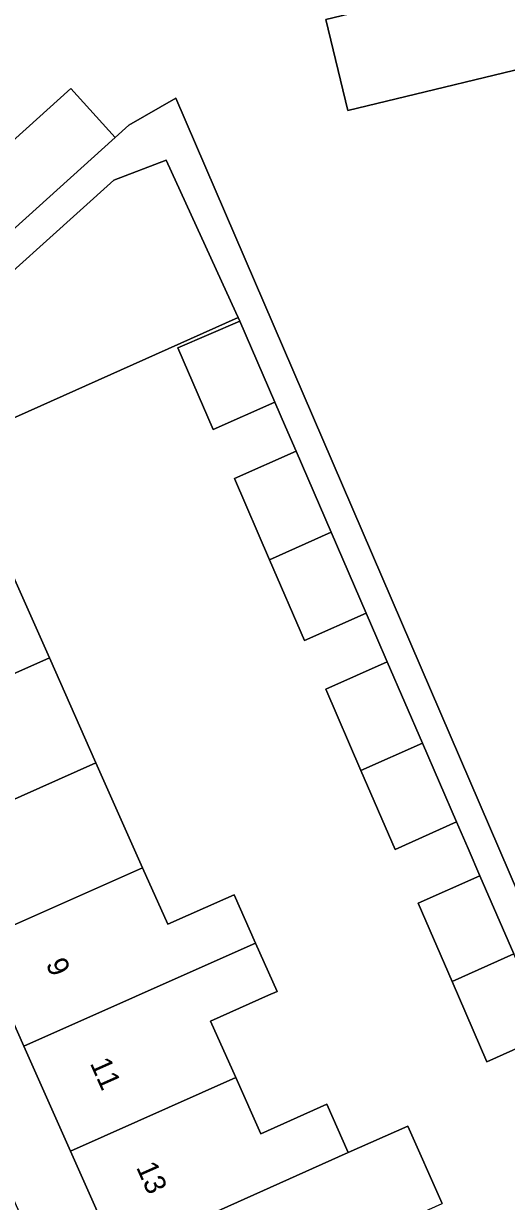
# Model space of a CAD drawing. Extents: x 163147 to 163550, y 380933 to 381639.
# Drawn here: x 163282.6 to 163305.4, y 381197.5 to 381253.2 of the extents above; entities that cross this region are included whole.
import ezdxf

# ---------------------------------------------------------------- set-up
doc = ezdxf.new("R2010")
doc.units = 0
for name, color, linetype in [('IMGEO_Erf', 7, 'Continuous'), ('IMGEO_Pand', 7, 'Continuous'), ('IMGEO_Pand_nummerreeks', 7, 'Continuous'), ('IMGEO_Voetpad_open', 7, 'Continuous')]:
    doc.layers.add(name, color=color, linetype=linetype)

msp = doc.modelspace()

# ---------------------------------------------------------------- linework, layer by layer
at = {"layer": 'IMGEO_Erf'}
for points in [[(163260.133, 381260.084), (163267.4, 381252.354), (163267.219, 381252.189), (163267.042, 381252.027), (163267.537, 381251.485), (163268.019, 381250.956), (163270.516, 381253.234), (163278.474, 381244.372), (163284.814, 381250.091), (163286.908, 381247.77), (163287.555, 381248.354), (163289.781, 381249.639), (163311.555, 381199.092)], [(163307.393, 381205.408), (163304.487, 381204.106), (163302.844, 381207.901), (163301.242, 381211.6), (163304.15, 381212.895), (163303.595, 381214.178), (163303.052, 381215.432), (163300.144, 381214.137), (163298.53, 381217.864), (163296.867, 381221.702), (163299.776, 381222.996), (163299.281, 381224.139), (163298.776, 381225.305), (163295.867, 381224.011), (163294.215, 381227.826), (163292.556, 381231.656), (163295.466, 381232.949), (163294.967, 381234.1), (163294.464, 381235.263), (163291.554, 381233.97), (163289.881, 381237.834), (163292.803, 381239.099), (163292.732, 381239.262), (163281.127, 381234.095)], [(163287.005, 381194.915), (163284.8, 381199.874), (163282.595, 381204.834), (163280.39, 381209.794), (163278.184, 381214.754), (163275.979, 381219.714), (163273.773, 381224.674), (163271.388, 381230.039), (163267.96, 381228.115), (163270.156, 381224.203), (163305.202, 381146.131)], [(163281.602, 381228.156), (163283.805, 381223.195), (163286.007, 381218.234), (163288.21, 381213.273), (163289.398, 381210.597), (163292.139, 381211.816), (163292.534, 381211.992), (163293.55, 381209.708), (163294.566, 381207.424), (163294.169, 381207.247), (163291.427, 381206.027), (163292.616, 381203.351), (163293.795, 381200.695), (163296.92, 381202.094), (163297.934, 381199.81), (163300.743, 381201.067), (163302.37, 381197.403)]]:
    msp.add_lwpolyline(points, dxfattribs=at)
for points in [[(163307.445, 381255.9), (163308.483, 381251.605), (163297.911, 381249.049), (163296.872, 381253.344)], [(163292.732, 381239.262), (163292.625, 381239.51), (163289.321, 381246.708), (163286.852, 381245.76), (163279.044, 381238.73), (163271.048, 381231.531), (163271.253, 381231.167), (163280.578, 381235.316), (163281.127, 381234.095)]]:
    msp.add_lwpolyline(points, close=True, dxfattribs=at)
at = {"layer": 'IMGEO_Pand'}
for points in [[(163308.483, 381251.605), (163307.445, 381255.9), (163296.872, 381253.344), (163297.911, 381249.049)], [(163278.474, 381244.372), (163280.568, 381242.051), (163286.908, 381247.77), (163284.814, 381250.091)], [(163292.803, 381239.099), (163289.881, 381237.834), (163291.554, 381233.97), (163294.464, 381235.263)], [(163295.466, 381232.949), (163292.556, 381231.656), (163294.215, 381227.826), (163297.124, 381229.12)], [(163297.124, 381229.12), (163294.215, 381227.826), (163295.867, 381224.011), (163298.776, 381225.305)], [(163281.602, 381228.156), (163273.773, 381224.674), (163275.979, 381219.714), (163283.805, 381223.195)], [(163278.184, 381214.754), (163286.007, 381218.234), (163283.805, 381223.195), (163275.979, 381219.714)], [(163299.776, 381222.996), (163296.867, 381221.702), (163298.53, 381217.864), (163301.439, 381219.158)], [(163301.439, 381219.158), (163298.53, 381217.864), (163300.144, 381214.137), (163303.052, 381215.432)], [(163278.184, 381214.754), (163280.39, 381209.794), (163288.21, 381213.273), (163286.007, 381218.234)], [(163293.55, 381209.708), (163292.534, 381211.992), (163292.139, 381211.816), (163289.398, 381210.597), (163288.21, 381213.273), (163280.39, 381209.794), (163282.595, 381204.834), (163293.154, 381209.532)], [(163304.15, 381212.895), (163301.242, 381211.6), (163302.844, 381207.901), (163305.753, 381209.195)], [(163291.427, 381206.027), (163294.169, 381207.247), (163294.566, 381207.424), (163293.55, 381209.708), (163293.154, 381209.532), (163282.595, 381204.834), (163284.8, 381199.874), (163292.616, 381203.351)], [(163305.753, 381209.195), (163302.844, 381207.901), (163304.487, 381204.106), (163307.393, 381205.408)], [(163297.934, 381199.81), (163296.92, 381202.094), (163293.795, 381200.695), (163292.616, 381203.351), (163284.8, 381199.874), (163287.005, 381194.915)], [(163290.18, 381188.516), (163297.586, 381191.811), (163297.507, 381191.987), (163301.823, 381193.924), (163300.616, 381196.616), (163302.37, 381197.403), (163300.743, 381201.067), (163297.934, 381199.81), (163287.005, 381194.915), (163289.272, 381189.817), (163289.547, 381189.939)]]:
    msp.add_lwpolyline(points, close=True, dxfattribs=at)
at = {"layer": 'IMGEO_Voetpad_open'}
for points in [[(163311.555, 381199.092), (163289.781, 381249.639), (163287.555, 381248.354), (163286.908, 381247.77), (163280.568, 381242.051)], [(163279.044, 381238.73), (163286.852, 381245.76), (163289.321, 381246.708), (163292.625, 381239.51), (163292.732, 381239.262), (163292.803, 381239.099), (163294.464, 381235.263), (163294.967, 381234.1), (163295.466, 381232.949), (163297.124, 381229.12), (163298.776, 381225.305), (163299.281, 381224.139), (163299.776, 381222.996), (163301.439, 381219.158), (163303.052, 381215.432), (163303.595, 381214.178), (163304.15, 381212.895), (163305.753, 381209.195)]]:
    msp.add_lwpolyline(points, dxfattribs=at)

# ---------------------------------------------------------------- texts
at = {"layer": 'IMGEO_Pand_nummerreeks'}
for s, rotation, p in [('9', 293.9723, (163283.619, 381208.734)), ('11', 293.9723, (163285.709, 381204.033)), ('13', 293.9715, (163287.894, 381199.119))]:
    msp.add_text(s, height=1, rotation=rotation, dxfattribs=at).set_placement(p)

doc.saveas('drawing.dxf')
